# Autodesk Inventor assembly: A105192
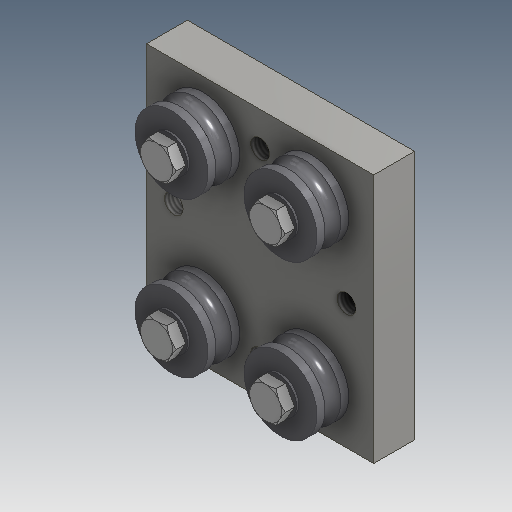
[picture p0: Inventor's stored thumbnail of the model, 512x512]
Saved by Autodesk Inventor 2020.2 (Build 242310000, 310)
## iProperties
Created: 2000-01
Part Number: A105192
Description: BEARING,TRACK,ROLLER,INA LFL 20 SF
Document SubType Name: Assembly
Designer: glanglot
Mass: 111.99 g
Surface Area: 129.75 cm^2
Volume: 29.955 cm^3
Density: 3.73862 g/cm^3
Control State: 0
Checked Out: False
Master: False
Shininess: 0.0
Length Units: 11269
Angle Units: 11279
Time Units: 11290
Mass Units: 11283
Length Display Precision: 3
Angle Display Precision: 2
Compacted: True
Dimensions: 55x19,8x50 mm
Mass: 0,112 kg
DocNumber: A105192.iam
Folder: 01 - Themengebiete\Simplification\01 - Packaging machine\
VDS_Category: 3D Komponenten
Density: 0.0
Volumn: 0.0
Area: 0.0
PropertySet Name: Model Information
Author: glanglot
Revision Number: -
Title: BEARING,TRACK,ROLLER,INA LFL 20 SF
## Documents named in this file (4)
- D:\07 - DEMODATEN\OTX 2019 - Dataset - UPDATE - Dez2019\Designs\07-Packing machine\A105192.iam
- D:\07 - DEMODATEN\OTX 2019 - Dataset - UPDATE - Dez2019\Designs\07-Packing machine\Parts\ADSK-011803.ipt
- D:\07 - DEMODATEN\OTX 2019 - Dataset - UPDATE - Dez2019\Designs\07-Packing machine\Parts\ADSK-011805.ipt
- D:\07 - DEMODATEN\OTX 2019 - Dataset - UPDATE - Dez2019\Content Center Files\de-DE\DIN EN 24 017\ISO 4017 - M4 x 16DIN EN.ipt
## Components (9 placed, 3 different names)
1. ADSK-011803:1 — Insert:1, Insert:2, Insert:3, Insert:4
2. ADSK-011805:1 — Insert:1
3. ADSK-011805:2 — Insert:2, Passend:2, Passend:4, Passend:6, Passend:8
4. ADSK-011805:3 — Insert:3
5. ADSK-011805:4 — Insert:4
6. DIN EN 24017 M4 x 16:1 — Passend:2
7. DIN EN 24017 M4 x 16:2 — Passend:4
8. DIN EN 24017 M4 x 16:3 — Passend:6
9. DIN EN 24017 M4 x 16:4 — Passend:8
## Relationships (8: Insert 4, Mate 4)
- Insert:1: ADSK-011803:1 ↔ ADSK-011805:1
- Insert:2: ADSK-011803:1 ↔ ADSK-011805:2
- Insert:3: ADSK-011803:1 ↔ ADSK-011805:3
- Insert:4: ADSK-011803:1 ↔ ADSK-011805:4
- Passend:2 [Mate]: ADSK-011805:2 ↔ DIN EN 24017 M4 x 16:1
- Passend:4 [Mate]: ADSK-011805:2 ↔ DIN EN 24017 M4 x 16:2
- Passend:6 [Mate]: ADSK-011805:2 ↔ DIN EN 24017 M4 x 16:3
- Passend:8 [Mate]: ADSK-011805:2 ↔ DIN EN 24017 M4 x 16:4
